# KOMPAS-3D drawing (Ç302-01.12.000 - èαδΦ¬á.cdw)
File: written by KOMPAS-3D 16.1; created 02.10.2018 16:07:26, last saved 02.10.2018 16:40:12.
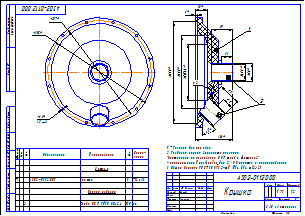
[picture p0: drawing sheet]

Sheet 1: A3, landscape

Title block, sheet 1: name: Крышка; designation: А302-01.12.000; mass: 1,73; scale: 1:2; sheets: 1; organisation: ЗАО «Астерион»; sheet format: A3; stored path: \\192.168.87.28\Konstructor_doc\Мембранные насосы\Мембранный электропривод\А302-00.00.000 - ASTRA-302 (МЭ200)\3Д ПВХ\А302-01.12.000 - Крышка.cdw; drawn by: Милов; technical control: Лучихин

Views: Вид 1, Местный разрез 1, Спереди, Проекционный вид 2, Вид:1
Referenced files in \\192.168.87.28\Konstructor_doc\Мембранные насосы\Мембранный электропривод\А302-00.00.000 - ASTRA-302 (МЭ200)\3Д ПВХ\Отработка\: Труба ПВХ PN10 50х2,4.m3d
Referenced files in \\192.168.87.28\Konstructor_doc\Мембранные насосы\Мембранный электропривод\А302-00.00.000 - ASTRA-302 (МЭ200)\3Д ПВХ\: А302-01.12.001 - Крышка.m3d, А302-01.12.000 - Крышка.a3d
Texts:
  *Размеры для справок.
  Разделку кромок выполнить согласно:
  "Инструкция по склеиванию ПВХ труб и фитингов".
  - расположение Konstructor_doc Z:\5 Оснастка и приспособления
  Общие допуски ГОСТ 30893.2-mK (H14, h14,  t2/2).
  Труба ПВХ PN10 50х2,4
Dimensions and other numbers on the sheet: 59; 31; 62; 45,2; 50; 33; 6; 280; 155,43; 202; 104; 1; 2; 302; 6,5; 12 отв.; 287; 1:2; 1,73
